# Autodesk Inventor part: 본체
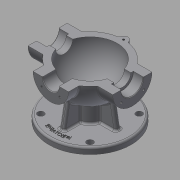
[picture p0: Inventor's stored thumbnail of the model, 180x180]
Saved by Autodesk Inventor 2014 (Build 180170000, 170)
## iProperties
Created: 2015-12
Part Number: 본체
Material: 알루미늄 6061
Document SubType Name: Modeling
Designer: mduedu
Density: 2.71 g/cm^3
Appearance: 알루미늄 - 평지
Mass: 966.367 g
Surface Area: 788.536 cm^2
Volume: 356.593 cm^3
Author: mduedu
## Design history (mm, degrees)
sketch "스케치1"
  geometry: L1 (-53, 0)-(53, 0); A1 r 53 centre (0, 0) between (53, 0) and (-53, 0); 2 further points
  constraints: 2 coincident, 2 end point, 2 point on circle, 1 centre point, 1 horizontal, 1 midpoint
  dimensions: "d0" = 53 radius of A1
revolve "회전1" sketch "스케치1" stored, may be unused: angle "d2" = 90 deg
feature "쉘1" dims "d11" = 10
node "작업 평면1"
sketch "스케치2"
  geometry: C1 r 31 at (0, 0); 1 further point
  constraints: 1 centre point, 1 coincident
  dimensions: "d4" = 62 diameter of C1
extrude "돌출1" join sketch "스케치2" stored distance "d5" = 10; taper "d6" = 0 deg
node "작업 평면2"
sketch "스케치3"
  geometry: C1 r 28 at (0, 0); 1 further point
  constraints: 1 centre point, 1 coincident
  dimensions: "d8" = 56 diameter of C1
extrude "돌출2" join sketch "스케치3" stored distance "d9" = 10; taper "d10" = 0 deg
hole "구멍1" diameter "d14" = 35; stored, may be unused: countersink angle "d18" = 90 deg, drill point angle "d20" = 0 deg; dims "d12" = 10, "d13" = 10, "d15" = 6, "d16" = 4, "d17" = 2, "d19" = 16
hole "구멍2" diameter "d23" = 27; stored, may be unused: countersink angle "d27" = 90 deg, drill point angle "d29" = 0 deg; dims "d21" = 10, "d22" = 10, "d24" = 6, "d25" = 4, "d26" = 2, "d28" = 16
fillet "모깎기1" dims "d30" = 0.3
hole "구멍3" diameter "d33" = 26; stored, may be unused: countersink angle "d37" = 90 deg, drill point angle "d39" = 0 deg; dims "d31" = 10, "d32" = 10, "d34" = 6, "d35" = 4, "d36" = 2, "d38" = 16
chamfer "모따기1" distance "d40" = 1; stored, may be unused: second distance "d41" = 2, angle "d42" = 45 deg
sketch "스케치4"
  geometry: L1 (0, 0)-(0, -25); L2 (0, 0)-(-17.678, -17.678); A1 r 25 centre (0, 0) between (-17.678, -17.678) and (0, -25); 1 further point
  constraints: 4 end point, 2 point on circle, 1 centre point, 1 coincident, 1 vertical
  dimensions: "d43" = 50 diameter of A1; "d47" = 45 deg angle of L1 L2
hole "구멍4" sketch "스케치4" at (-17.678, -17.678) diameter "d49" = 3.242; stored, may be unused: countersink angle "d53" = 90 deg, drill point angle "d55" = 118 deg; dims "d50" = 11, "d51" = 4, "d52" = 2, "d54" = 13
sketch "스케치5"
  geometry: L1 (0, 0)-(0, -20); L2 (0, 0)-(-14.142, -14.142); A1 r 20 centre (0, 0) between (0, -20) and (-14.142, -14.142); 2 further points
  constraints: 4 end point, 2 coincident, 2 point on circle, 1 centre point, 1 vertical
  dimensions: "d59" = 40 diameter of A1; "d65" = 45 deg angle of L1 L2
hole "구멍5" sketch "스케치5" at (-14.142, -14.142) diameter "d67" = 3.242; stored, may be unused: countersink angle "d71" = 90 deg, drill point angle "d73" = 118 deg; dims "d68" = 8, "d69" = 4, "d70" = 2, "d72" = 10
node "작업 평면3"
sketch "스케치6"
  geometry: C1 r 65 at (0, 0); 1 further point
  constraints: 1 centre point, 1 coincident
  dimensions: "d78" = 130 diameter of C1
extrude "돌출3" join sketch "스케치6" distance "d80" = 10; taper "d81" = 0 deg
sketch "스케치7"
  geometry: C1 r 20 at (0, 0); 1 further point
  constraints: 1 centre point, 1 coincident
  dimensions: "d82" = 40 diameter of C1
extrude "돌출4" join sketch "스케치7" stored distance "d84" = 10; taper "d85" = 0 deg
sketch "스케치8"
  geometry: 2 further points
  constraints: 1 coincident
hole "구멍6" sketch "스케치8" at (0, 0) diameter "d86" = 20; stored, may be unused: countersink angle "d90" = 90 deg, drill point angle "d92" = 118 deg; dims "d87" = 7, "d88" = 40, "d89" = 5, "d91" = 10
fillet "모깎기2" dims "d93" = 0.3
sketch "스케치9"
  geometry: L1 (65, -75)-(-65, -75) reference; L2 (-45, -75)-(-38.245, -36.692); A1 r 53 centre (0, 0) between (42.988, 31) and (42.988, -31) reference; 1 further point
  constraints: 2 end point, 1 point on circle, 1 point on line
  dimensions: "d94" = 45 horizontal distance of L2.start point (0, 0); "d95" = 80 deg angle of L2 L1
feature "리브1" sketch "스케치9" dims "d96" = 1, "d97" = 8, "d98" = 0, "d99" = 0, "d100" = 1, "d101" = 1
sketch "스케치10"
  geometry: L1 (0, 0)-(0, -55); L2 (0, 0)-(-38.891, -38.891); A1 r 55 centre (0, 0) between (0, -55) and (-38.891, -38.891); 2 further points
  constraints: 4 end point, 2 coincident, 2 point on circle, 1 centre point, 1 vertical
  dimensions: "d105" = 110 diameter of A1; "d107" = 45 deg angle of L1 L2
hole "구멍7" sketch "스케치10" at (-38.891, -38.891) diameter "d109" = 10; stored, may be unused: countersink angle "d113" = 90 deg, drill point angle "d115" = 118 deg; dims "d110" = 7, "d111" = 40, "d112" = 5, "d114" = 10
fillet "모깎기3" dims "d120" = 3
fillet "모깎기4" dims "d121" = 3, "d122" = 3
fillet "모깎기5" dims "d123" = 3
fillet "모깎기6" dims "d124" = 3
sketch "스케치11"
  geometry: C1 r 5 at (-38.891, 38.891) reference; C2 r 5 at (38.891, 38.891) reference; C3 r 5 at (38.891, -38.891) reference; C4 r 5 at (-38.891, -38.891) reference; C5 r 20 at (0, 0) reference; C6 r 65 at (0, 0) reference; 1 further point
  constraints: 3 other
feature "엠보싱1" sketch "스케치11" dims "d125" = 0.5, "d126" = 0
sketch "스케치12"
  geometry: L1 (0, 100)-(0, -100); L2 (0, 100)-(100, 100); L3 (100, 100)-(100, -100); L4 (100, -100)-(0, -100); 2 further points
  constraints: 8 end point, 3 perpendicular, 1 coincident, 1 midpoint, 1 vertical
  dimensions: "d127" = 200 distance of L2.end L3.end; "d129" = 100 distance between parallel lines of L1 L3
extrude "돌출5" cut sketch "스케치12" stored distance "d130" = 10; taper "d131" = 0 deg
sketch "스케치13"
  geometry: C1 r 7 at (0, 53); A1 r 53 centre (0, 0) between (42.113, 32.179) and (-42.113, 32.179) reference; 1 further point
  constraints: 1 centre point, 1 point on circle
  dimensions: "d132" = 14 diameter of C1
extrude "돌출6" join sketch "스케치13" distance "d134" = 15; taper "d135" = 0 deg
hole "구멍8" diameter "d139" = 3.242; stored, may be unused: countersink angle "d143" = 90 deg, drill point angle "d145" = 118 deg; dims "d140" = 8, "d141" = 4, "d142" = 2, "d144" = 10, "d148" = 10, "d149" = 10
fillet "모깎기7" dims "d146" = 3
fillet "모깎기8" dims "d147" = 3
node "솔리드1"
mirror "대칭1"
mirror "대칭2"
pattern_circular "원형 패턴1" dims angle "d57" = 360 deg
mirror "대칭3"
pattern_circular "원형 패턴2" dims angle "d75" = 360 deg
pattern_circular "원형 패턴3" dims angle "d103" = 360 deg
pattern_circular "원형 패턴4" dims angle "d118" = 360 deg
node "투영된 루프1"
other parameters: "d3" = 67, "d7" = 62, "d77" = -85
